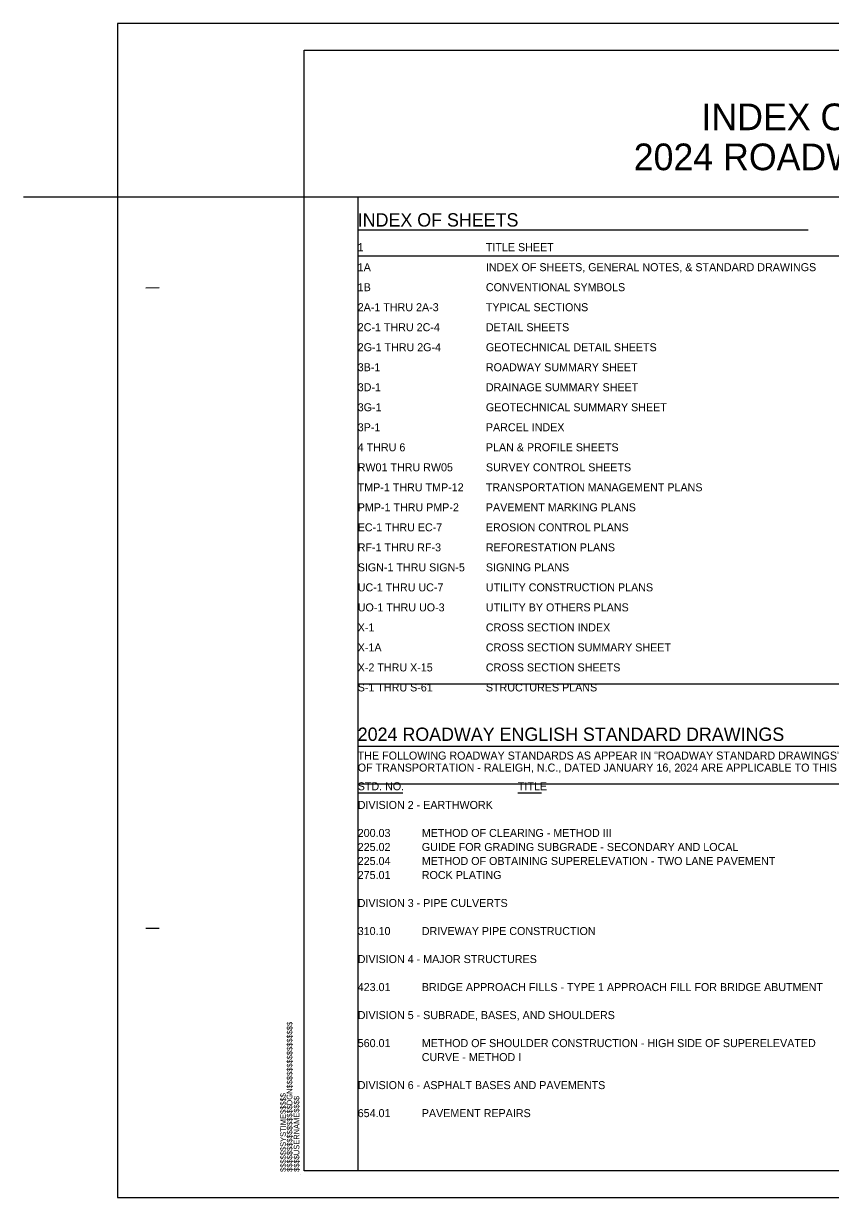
# Model space of a CAD drawing. Extents: x 573076.3 to 573113.7, y -55253.8 to -55199.3.
# Drawn here: x 573076.25 to 573091.37, y -55221.3 to -55199.3 of the extents above; entities that cross this region are included whole.
import ezdxf

# ---------------------------------------------------------------- set-up
doc = ezdxf.new("R2010")
doc.units = 0
for name, color, linetype in [('Prop DSN Text', 7, 'Continuous'), ('Scratch_Level_1', 7, 'Continuous'), ('Sheet Data Field CELL', 7, 'Continuous'), ('Sheet Plan CELL', 7, 'Continuous'), ('Sheet Plot Border Inside CELL', 7, 'Continuous')]:
    doc.layers.add(name, color=color, linetype=linetype)

msp = doc.modelspace()

# ---------------------------------------------------------------- linework, layer by layer
at = {"layer": 'Prop DSN Text'}
for p, q in [((573082.514, -55203.165), (573090.951, -55203.165)), ((573082.514, -55212.842), (573096.001, -55212.842)), ((573082.514, -55213.717), (573083.356, -55213.717)), ((573085.514, -55213.717), (573085.957, -55213.717))]:
    msp.add_line(p, q, dxfattribs=at)
at = {"layer": 'Scratch_Level_1'}
for p, q in [((573111.514, -55202.55), (573076.255, -55202.55)), ((573082.514, -55202.55), (573082.514, -55220.798)), ((573082.514, -55203.65), (573112.708, -55203.65)), ((573082.514, -55211.674), (573113.454, -55211.674)), ((573082.514, -55213.549), (573113.722, -55213.549))]:
    msp.add_line(p, q, dxfattribs=at)
at = {"layer": 'Sheet Plan CELL'}
for p, q in [((573081.514, -55199.798), (573081.514, -55199.798)), ((573078.544, -55204.249), (573078.794, -55204.248)), ((573078.545, -55216.249), (573078.795, -55216.249)), ((573081.443, -55220.864), (573081.443, -55220.864))]:
    msp.add_line(p, q, dxfattribs=at)
msp.add_lwpolyline([(573081.514, -55199.798), (573111.514, -55199.798), (573111.514, -55220.798), (573081.514, -55220.798)], close=True, dxfattribs=at)
at = {"layer": 'Sheet Plot Border Inside CELL'}
msp.add_lwpolyline([(573112.014, -55199.298), (573078.014, -55199.298), (573078.014, -55221.298), (573112.014, -55221.298)], close=True, dxfattribs=at)

# ---------------------------------------------------------------- texts
at = {"layer": 'Prop DSN Text'}
for s, height, p in [('INDEX OF SHEETS', 0.25, (573082.514, -55203.104)), ('1', 0.15, (573082.514, -55203.565)), ('TITLE SHEET', 0.15, (573084.914, -55203.565)), ('1A', 0.15, (573082.514, -55203.94)), ('INDEX OF SHEETS, GENERAL NOTES, & STANDARD DRAWINGS', 0.15, (573084.914, -55203.94)), ('1B', 0.15, (573082.514, -55204.315)), ('CONVENTIONAL SYMBOLS', 0.15, (573084.914, -55204.315)), ('2A-1 THRU 2A-3', 0.15, (573082.514, -55204.69)), ('TYPICAL SECTIONS', 0.15, (573084.914, -55204.69)), ('2C-1 THRU 2C-4', 0.15, (573082.514, -55205.065)), ('DETAIL SHEETS', 0.15, (573084.914, -55205.065)), ('2G-1 THRU 2G-4', 0.15, (573082.514, -55205.44)), ('GEOTECHNICAL DETAIL SHEETS', 0.15, (573084.914, -55205.44)), ('3B-1', 0.15, (573082.514, -55205.815)), ('ROADWAY SUMMARY SHEET', 0.15, (573084.914, -55205.815)), ('3D-1', 0.15, (573082.514, -55206.19)), ('DRAINAGE SUMMARY SHEET', 0.15, (573084.914, -55206.19)), ('3G-1', 0.15, (573082.514, -55206.565)), ('GEOTECHNICAL SUMMARY SHEET', 0.15, (573084.914, -55206.565)), ('3P-1', 0.15, (573082.514, -55206.94)), ('PARCEL INDEX', 0.15, (573084.914, -55206.94)), ('4 THRU 6', 0.15, (573082.514, -55207.315)), ('PLAN & PROFILE SHEETS', 0.15, (573084.914, -55207.315)), ('RW01 THRU RW05', 0.15, (573082.514, -55207.69)), ('SURVEY CONTROL SHEETS', 0.15, (573084.914, -55207.69)), ('TMP-1 THRU TMP-12', 0.15, (573082.514, -55208.065)), ('TRANSPORTATION MANAGEMENT PLANS', 0.15, (573084.914, -55208.065)), ('PMP-1 THRU PMP-2', 0.15, (573082.514, -55208.44)), ('PAVEMENT MARKING PLANS', 0.15, (573084.914, -55208.44)), ('EC-1 THRU EC-7', 0.15, (573082.514, -55208.815)), ('EROSION CONTROL PLANS', 0.15, (573084.914, -55208.815)), ('RF-1 THRU RF-3', 0.15, (573082.514, -55209.19)), ('REFORESTATION PLANS', 0.15, (573084.914, -55209.19)), ('SIGN-1 THRU SIGN-5', 0.15, (573082.514, -55209.565)), ('SIGNING PLANS', 0.15, (573084.914, -55209.565)), ('UC-1 THRU UC-7', 0.15, (573082.514, -55209.94)), ('UTILITY CONSTRUCTION PLANS', 0.15, (573084.914, -55209.94)), ('UO-1 THRU UO-3', 0.15, (573082.514, -55210.315)), ('UTILITY BY OTHERS PLANS', 0.15, (573084.914, -55210.315)), ('CROSS SECTION INDEX', 0.15, (573084.914, -55210.69)), ('X-1', 0.15, (573082.514, -55210.69)), ('X-1A', 0.15, (573082.514, -55211.065)), ('CROSS SECTION SUMMARY SHEET', 0.15, (573084.914, -55211.065)), ('X-2 THRU X-15', 0.15, (573082.514, -55211.44)), ('CROSS SECTION SHEETS', 0.15, (573084.914, -55211.44)), ('S-1 THRU S-61', 0.15, (573082.514, -55211.815)), ('STRUCTURES PLANS', 0.15, (573084.914, -55211.815)), ('2024 ROADWAY ENGLISH STANDARD DRAWINGS', 0.25, (573082.514, -55212.742)), ('THE FOLLOWING ROADWAY STANDARDS AS APPEAR IN "ROADWAY STANDARD DRAWINGS" CONTRACTS STANDARDS AND DEVELOPEMENT UNIT - N.C. DEPARTMENT', 0.15, (573082.514, -55213.092)), ('OF TRANSPORTATION - RALEIGH, N.C., DATED JANUARY 16, 2024 ARE APPLICABLE TO THIS PROJECT AND BY REFERENCE HEREBY ARE CONSIDERED A PART OF THESE PLANS:', 0.15, (573082.514, -55213.317)), ('STD. NO.', 0.15, (573082.514, -55213.667)), ('TITLE', 0.15, (573085.514, -55213.667)), ('DIVISION 2 - EARTHWORK', 0.15, (573082.514, -55214.017)), ('200.03', 0.15, (573082.514, -55214.542)), ('METHOD OF CLEARING - METHOD III', 0.15, (573083.714, -55214.542)), ('225.02', 0.15, (573082.514, -55214.805)), ('GUIDE FOR GRADING SUBGRADE - SECONDARY AND LOCAL', 0.15, (573083.714, -55214.805)), ('225.04', 0.15, (573082.514, -55215.067)), ('METHOD OF OBTAINING SUPERELEVATION - TWO LANE PAVEMENT', 0.15, (573083.714, -55215.067)), ('275.01', 0.15, (573082.514, -55215.33)), ('ROCK PLATING', 0.15, (573083.714, -55215.33)), ('DIVISION 3 - PIPE CULVERTS', 0.15, (573082.514, -55215.855)), ('310.10', 0.15, (573082.514, -55216.38)), ('DRIVEWAY PIPE CONSTRUCTION', 0.15, (573083.714, -55216.38)), ('DIVISION 4 - MAJOR STRUCTURES', 0.15, (573082.514, -55216.905)), ('423.01', 0.15, (573082.514, -55217.43)), ('BRIDGE APPROACH FILLS - TYPE 1 APPROACH FILL FOR BRIDGE ABUTMENT', 0.15, (573083.714, -55217.43)), ('DIVISION 5 - SUBRADE, BASES, AND SHOULDERS', 0.15, (573082.514, -55217.955)), ('560.01', 0.15, (573082.514, -55218.48)), ('METHOD OF SHOULDER CONSTRUCTION - HIGH SIDE OF SUPERELEVATED', 0.15, (573083.714, -55218.48)), ('CURVE - METHOD I', 0.15, (573083.714, -55218.742)), ('DIVISION 6 - ASPHALT BASES AND PAVEMENTS', 0.15, (573082.514, -55219.267)), ('654.01', 0.15, (573082.514, -55219.792)), ('PAVEMENT REPAIRS', 0.15, (573083.714, -55219.792))]:
    msp.add_text(s, height=height, dxfattribs=at).set_placement(p)
at = {"layer": 'Sheet Data Field CELL'}
for s, p in [('INDEX OF SHEETS, GENERAL NOTES AND', (573088.952, -55201.298)), ('2024 ROADWAY ENGLISH STANDARD DRAWINGS', (573087.683, -55202.048))]:
    msp.add_text(s, height=0.5, dxfattribs=at).set_placement(p)
at = {"layer": 'Sheet Plan CELL'}
for s, p in [('$$$$$$$$$$$$$$$$DGN$$$$$$$$$$$$$$$$', (573081.29, -55220.817)), ('$$$$$$SYSTIME$$$$$', (573081.169, -55220.818)), ('$$$$USERNAME$$$$', (573081.421, -55220.817))]:
    msp.add_text(s, height=0.105, rotation=90, dxfattribs=at).set_placement(p)

doc.saveas('drawing.dxf')
